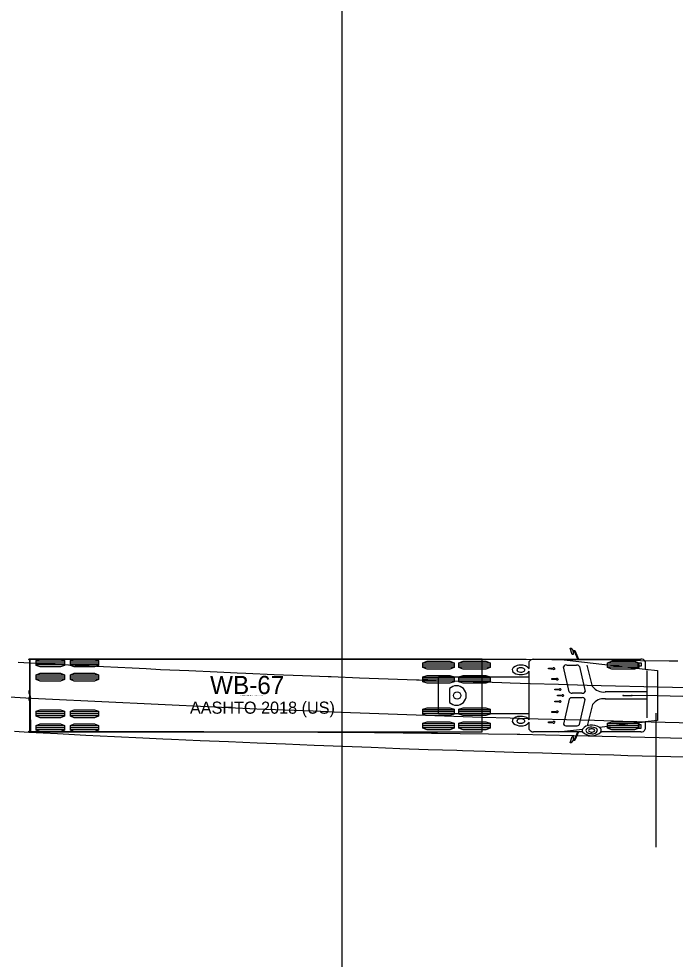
# Model space of a CAD drawing. Extents: x 973688 to 979179, y 703586 to 707602.
# Drawn here: x 977480.7 to 977557.4, y 704315.4 to 704425.4 of the extents above; entities that cross this region are included whole.
import ezdxf

# ---------------------------------------------------------------- set-up
doc = ezdxf.new("R2010")
doc.units = 0
for name, color, linetype in [('0-NPLT', 7, 'Continuous'), ('NO PLOT', 7, 'Continuous'), ('SB Left', 7, 'Continuous')]:
    doc.layers.add(name, color=color, linetype=linetype)

msp = doc.modelspace()

# ---------------------------------------------------------------- linework, layer by layer
at = {"layer": '0-NPLT'}
for points in [[(977480.64, 704350.16), (977483.97, 704349.98), (977484.96, 704349.93), (977487.29, 704349.81), (977490.62, 704349.65), (977493.94, 704349.49), (977495.6, 704349.41), (977497.26, 704349.33), (977500.59, 704349.18), (977503.91, 704349.03), (977506.24, 704348.93), (977507.24, 704348.88), (977510.56, 704348.74), (977513.89, 704348.61), (977516.88, 704348.49), (977517.21, 704348.48), (977520.54, 704348.35), (977523.87, 704348.23), (977527.19, 704348.11), (977527.52, 704348.1), (977530.52, 704348), (977533.84, 704347.89), (977537.17, 704347.78), (977538.16, 704347.75), (977540.49, 704347.68), (977543.82, 704347.58), (977547.14, 704347.49), (977548.8, 704347.45), (977550.47, 704347.4), (977553.79, 704347.32), (977557.12, 704347.24), (977559.78, 704347.18)], [(977558.6, 704339.07), (977555.26, 704339.15), (977551.92, 704339.23), (977550.26, 704339.28), (977548.59, 704339.32), (977545.25, 704339.41), (977541.92, 704339.51), (977538.58, 704339.61), (977535.25, 704339.71), (977532.58, 704339.8), (977531.91, 704339.82), (977528.58, 704339.93), (977525.24, 704340.05), (977521.9, 704340.17), (977518.57, 704340.29), (977515.23, 704340.42), (977511.9, 704340.56), (977508.56, 704340.69), (977505.22, 704340.84), (977501.89, 704340.98), (977498.55, 704341.13), (977497.55, 704341.18), (977495.22, 704341.29), (977491.88, 704341.45), (977488.55, 704341.61), (977485.21, 704341.78), (977481.88, 704341.95), (977480.21, 704342.04)]]:
    msp.add_lwpolyline(points, dxfattribs=at)
msp.add_arc((977617.27, 706926.99), 2584.55, 266.85786, 271.5329, dxfattribs=at)
at = {"layer": 'NO PLOT'}
msp.add_lwpolyline([(977518.51, 704645.43), (978198.51, 704645.43), (978198.51, 704205.43), (977518.51, 704205.43)], close=True, dxfattribs=at)
at = {"layer": 'SB Left'}
for p, q in [((977545.42, 704351.08), (977545.16, 704351.8)), ((977545.16, 704351.8), (977545.17, 704351.8)), ((977545.17, 704351.8), (977545.28, 704351.8)), ((977545.28, 704351.8), (977545.29, 704351.8)), ((977545.29, 704351.8), (977545.52, 704351.48)), ((977545.52, 704351.08), (977545.42, 704351.08)), ((977545.52, 704351.48), (977545.53, 704351.48)), ((977545.54, 704351.43), (977545.52, 704351.08)), ((977545.54, 704351.46), (977545.53, 704351.48)), ((977545.53, 704351.48), (977545.61, 704351.48)), ((977545.54, 704351.43), (977545.54, 704351.46)), ((977545.62, 704351.43), (977545.54, 704351.43)), ((977545.54, 704351.43), (977545.54, 704351.43)), ((977545.66, 704351.42), (977545.62, 704351.43)), ((977545.62, 704351.43), (977545.62, 704351.43)), ((977545.62, 704351.43), (977545.62, 704351.43)), ((977546.06, 704350.52), (977545.66, 704351.42)), ((977545.66, 704351.42), (977545.66, 704351.42)), ((977545.75, 704351.44), (977546.16, 704350.53)), ((977482.02, 704350.52), (977481.95, 704350.52)), ((977481.95, 704350.52), (977481.95, 704350.5)), ((977481.95, 704350.48), (977481.95, 704350.48)), ((977481.95, 704350.48), (977481.95, 704346.84)), ((977482.02, 704342.02), (977482.02, 704350.52)), ((977487.68, 704350.52), (977482.02, 704350.52)), ((977486.03, 704350.29), (977482.73, 704350.29)), ((977486.03, 704350.07), (977482.73, 704350.07)), ((977486.03, 704349.84), (977482.73, 704349.84)), ((977490.03, 704350.29), (977486.73, 704350.29)), ((977490.03, 704350.07), (977486.73, 704350.07)), ((977490.03, 704349.84), (977486.73, 704349.84)), ((977534.88, 704350.52), (977487.68, 704350.52)), ((977531.61, 704350.04), (977527.94, 704350.04)), ((977531.61, 704349.82), (977527.94, 704349.82)), ((977535.81, 704350.04), (977532.14, 704350.04)), ((977535.81, 704349.82), (977532.14, 704349.82)), ((977534.88, 704346.27), (977534.88, 704350.52)), ((977540.38, 704349.41), (977540.38, 704350.25)), ((977540.89, 704350.52), (977546.06, 704350.52)), ((977543.82, 704350.52), (977553.95, 704349.36)), ((977544.77, 704349.83), (977545.9, 704349.83)), ((977546.06, 704350.52), (977546.17, 704350.52)), ((977546.16, 704350.53), (977546.17, 704350.52)), ((977546.17, 704350.52), (977553.43, 704350.52)), ((977547.8, 704347.34), (977547.17, 704349.81)), ((977553.21, 704350.04), (977549.54, 704350.04)), ((977553.21, 704349.82), (977549.54, 704349.82)), ((977553.11, 704350.11), (977553.47, 704350.11)), ((977553.11, 704349.7), (977553.11, 704350.11)), ((977553.47, 704350.11), (977553.47, 704349.7)), ((977553.95, 704350.23), (977553.95, 704349.37)), ((977531.61, 704349.59), (977527.94, 704349.59)), ((977535.81, 704349.59), (977532.14, 704349.59)), ((977540.38, 704348.44), (977540.38, 704349.13)), ((977542.65, 704349.46), (977543.2, 704349.5)), ((977542.65, 704349.37), (977542.65, 704349.46)), ((977543.2, 704349.33), (977542.65, 704349.37)), ((977545.04, 704346.7), (977544.4, 704349.63)), ((977546.27, 704349.67), (977546.91, 704346.73)), ((977553.21, 704349.59), (977549.54, 704349.59)), ((977553.47, 704349.7), (977553.11, 704349.7)), ((977553.95, 704349.37), (977553.95, 704349.36)), ((977553.95, 704349.36), (977555.38, 704349.2)), ((977554.17, 704343.64), (977554.17, 704349.2)), ((977555.38, 704349.2), (977555.38, 704349.14)), ((977555.38, 704349.14), (977555.38, 704346.27)), ((977486.03, 704348.64), (977482.73, 704348.64)), ((977486.03, 704348.42), (977482.73, 704348.42)), ((977486.03, 704348.19), (977482.73, 704348.19)), ((977490.03, 704348.64), (977486.73, 704348.64)), ((977490.03, 704348.42), (977486.73, 704348.42)), ((977490.03, 704348.19), (977486.73, 704348.19)), ((977531.61, 704348.39), (977527.94, 704348.39)), ((977531.61, 704348.17), (977527.94, 704348.17)), ((977531.61, 704347.94), (977527.94, 704347.94)), ((977529.78, 704346.27), (977529.78, 704348.44)), ((977529.78, 704348.44), (977540.14, 704348.44)), ((977535.81, 704348.39), (977532.14, 704348.39)), ((977535.81, 704348.17), (977532.14, 704348.17)), ((977535.81, 704347.94), (977532.14, 704347.94)), ((977540.14, 704348.44), (977540.38, 704348.44)), ((977540.38, 704344.11), (977540.38, 704348.44)), ((977543.04, 704348.24), (977543.61, 704348.28)), ((977543.04, 704348.15), (977543.04, 704348.24)), ((977543.61, 704348.11), (977543.04, 704348.15)), ((977481.95, 704346.8), (977481.88, 704346.8)), ((977481.88, 704346.8), (977481.88, 704346.8)), ((977481.88, 704346.8), (977481.88, 704346.54)), ((977481.95, 704346.84), (977481.95, 704346.8)), ((977481.95, 704346.54), (977481.95, 704346.8)), ((977481.95, 704346.53), (977481.95, 704346.01)), ((977531.07, 704347.08), (977531.07, 704345.46)), ((977543.37, 704347.02), (977543.92, 704347.06)), ((977543.37, 704346.94), (977543.37, 704347.02)), ((977543.92, 704346.9), (977543.37, 704346.94)), ((977546.54, 704346.53), (977545.41, 704346.53)), ((977554.17, 704346.69), (977549.28, 704346.69)), ((977481.88, 704346.01), (977481.88, 704345.74)), ((977481.88, 704345.74), (977481.88, 704345.74)), ((977481.88, 704345.74), (977481.95, 704345.74)), ((977481.95, 704346.27), (977482.02, 704346.27)), ((977481.95, 704345.74), (977481.95, 704346.01)), ((977481.95, 704345.74), (977481.95, 704345.71)), ((977481.95, 704345.71), (977481.95, 704342.07)), ((977529.78, 704344.11), (977529.78, 704346.27)), ((977534.88, 704342.02), (977534.88, 704346.27)), ((977543.37, 704345.61), (977543.92, 704345.65)), ((977543.37, 704345.52), (977543.37, 704345.61)), ((977543.92, 704345.48), (977543.37, 704345.52)), ((977543.68, 704346.32), (977544.23, 704346.36)), ((977543.68, 704346.23), (977543.68, 704346.32)), ((977544.23, 704346.19), (977543.68, 704346.23)), ((977545.04, 704345.85), (977544.4, 704342.91)), ((977546.54, 704346.01), (977545.41, 704346.01)), ((977546.27, 704342.88), (977546.91, 704345.82)), ((977554.17, 704345.86), (977549.28, 704345.86)), ((977555.38, 704346.27), (977555.38, 704343.41)), ((977486.03, 704344.36), (977482.73, 704344.36)), ((977490.03, 704344.36), (977486.73, 704344.36)), ((977531.61, 704344.61), (977527.94, 704344.61)), ((977531.61, 704344.38), (977527.94, 704344.38)), ((977535.81, 704344.61), (977532.14, 704344.61)), ((977535.81, 704344.38), (977532.14, 704344.38)), ((977543.04, 704344.39), (977543.58, 704344.43)), ((977543.04, 704344.3), (977543.04, 704344.39)), ((977543.58, 704344.27), (977543.04, 704344.3)), ((977547.8, 704345.2), (977547.17, 704342.72)), ((977486.03, 704344.13), (977482.73, 704344.13)), ((977486.03, 704343.9), (977482.73, 704343.9)), ((977490.03, 704344.13), (977486.73, 704344.13)), ((977490.03, 704343.9), (977486.73, 704343.9)), ((977531.61, 704344.15), (977527.94, 704344.15)), ((977540.14, 704344.11), (977529.78, 704344.11)), ((977535.81, 704344.15), (977532.14, 704344.15)), ((977540.38, 704344.11), (977540.14, 704344.11)), ((977540.38, 704343.42), (977540.38, 704344.11)), ((977542.65, 704343.18), (977543.2, 704343.22)), ((977555.38, 704343.35), (977553.95, 704343.18)), ((977555.19, 704344.19), (977555.19, 704328.54)), ((977555.38, 704343.41), (977555.38, 704343.35)), ((977486.03, 704342.71), (977482.73, 704342.71)), ((977486.03, 704342.48), (977482.73, 704342.48)), ((977486.03, 704342.25), (977482.73, 704342.25)), ((977490.03, 704342.71), (977486.73, 704342.71)), ((977490.03, 704342.48), (977486.73, 704342.48)), ((977490.03, 704342.25), (977486.73, 704342.25)), ((977531.61, 704342.96), (977527.94, 704342.96)), ((977531.61, 704342.73), (977527.94, 704342.73)), ((977531.61, 704342.5), (977527.94, 704342.5)), ((977535.81, 704342.96), (977532.14, 704342.96)), ((977535.81, 704342.73), (977532.14, 704342.73)), ((977535.81, 704342.5), (977532.14, 704342.5)), ((977540.38, 704342.29), (977540.38, 704343.14)), ((977542.65, 704343.09), (977542.65, 704343.18)), ((977543.2, 704343.05), (977542.65, 704343.09)), ((977543.82, 704342.02), (977546.6, 704342.34)), ((977544.77, 704342.72), (977545.9, 704342.72)), ((977548.56, 704342.57), (977553.95, 704343.18)), ((977553.21, 704342.96), (977549.54, 704342.96)), ((977553.21, 704342.73), (977549.54, 704342.73)), ((977553.21, 704342.5), (977549.54, 704342.5)), ((977553.47, 704342.85), (977553.11, 704342.85)), ((977553.11, 704342.85), (977553.11, 704342.43)), ((977553.11, 704342.43), (977553.47, 704342.43)), ((977553.47, 704342.43), (977553.47, 704342.85)), ((977553.95, 704343.18), (977553.95, 704343.18)), ((977553.95, 704343.18), (977553.95, 704342.32)), ((977481.95, 704342.07), (977481.95, 704342.07)), ((977481.95, 704342.05), (977481.95, 704342.02)), ((977481.95, 704342.02), (977482.02, 704342.02)), ((977482.02, 704342.02), (977487.68, 704342.02)), ((977487.68, 704342.02), (977534.88, 704342.02)), ((977546.06, 704342.02), (977540.89, 704342.02)), ((977545.16, 704340.74), (977545.42, 704341.46)), ((977545.52, 704341.06), (977545.29, 704340.74)), ((977545.42, 704341.46), (977545.52, 704341.46)), ((977545.52, 704341.46), (977545.54, 704341.12)), ((977545.53, 704341.06), (977545.52, 704341.06)), ((977545.54, 704341.09), (977545.53, 704341.06)), ((977545.61, 704341.06), (977545.53, 704341.06)), ((977545.54, 704341.12), (977545.54, 704341.11)), ((977545.54, 704341.11), (977545.62, 704341.12)), ((977545.54, 704341.11), (977545.54, 704341.09)), ((977545.62, 704341.12), (977545.66, 704341.13)), ((977545.62, 704341.12), (977545.62, 704341.12)), ((977545.62, 704341.12), (977545.62, 704341.12)), ((977545.66, 704341.13), (977546.06, 704342.02)), ((977545.66, 704341.13), (977545.66, 704341.13)), ((977546.16, 704342.01), (977545.75, 704341.11)), ((977546.06, 704342.02), (977546.17, 704342.02)), ((977546.17, 704342.02), (977546.16, 704342.01)), ((977546.6, 704342.02), (977546.17, 704342.02)), ((977553.43, 704342.02), (977548.78, 704342.02)), ((977545.17, 704340.74), (977545.16, 704340.74)), ((977545.28, 704340.74), (977545.17, 704340.74)), ((977545.29, 704340.74), (977545.28, 704340.74))]:
    msp.add_line(p, q, dxfattribs=at)
for points in [[(977481.99, 704350.52), (977482.88, 704350.52), (977483.99, 704350.52), (977485.1, 704350.52), (977486.21, 704350.52), (977487.32, 704350.52), (977489.99, 704350.52), (977493.32, 704350.52), (977496.65, 704350.52), (977499.99, 704350.52), (977503.32, 704350.52), (977506.65, 704350.52), (977509.99, 704350.52), (977513.32, 704350.52), (977516.66, 704350.52), (977519.99, 704350.52), (977523.33, 704350.52), (977526.66, 704350.52), (977530, 704350.52), (977533.34, 704350.52), (977535.68, 704350.52), (977536.68, 704350.52), (977540.02, 704350.51), (977543.02, 704350.5), (977543.36, 704350.5), (977546.7, 704350.47), (977550.05, 704350.43), (977550.38, 704350.43), (977553.4, 704350.38), (977556.74, 704350.32), (977557.75, 704350.31)], [(977558.21, 704341.25), (977555.56, 704341.32), (977552.24, 704341.41), (977548.92, 704341.49), (977545.6, 704341.56), (977542.28, 704341.63), (977539.29, 704341.69), (977538.96, 704341.69), (977535.63, 704341.75), (977532.3, 704341.8), (977529.64, 704341.83), (977528.97, 704341.84), (977525.64, 704341.88), (977522.31, 704341.91), (977519.98, 704341.93), (977518.98, 704341.94), (977515.65, 704341.96), (977512.32, 704341.98), (977509.65, 704341.99), (977508.99, 704341.99), (977505.65, 704342), (977502.32, 704342.01), (977498.99, 704342.02), (977495.65, 704342.02), (977492.32, 704342.02), (977488.99, 704342.02), (977486.99, 704342.02), (977485.88, 704342.02), (977484.76, 704342.02), (977483.65, 704342.02), (977482.54, 704342.02), (977482.1, 704342.02), (977481.99, 704350.52)], [(977551.38, 704346.27), (977551.71, 704346.27), (977552.04, 704346.27), (977552.38, 704346.27)]]:
    msp.add_lwpolyline(points, dxfattribs=at)
for points in [[(977486.03, 704350.35), (977486.03, 704349.78), (977485.56, 704349.61), (977483.19, 704349.61), (977482.73, 704349.78), (977482.73, 704350.35), (977483.19, 704350.52), (977485.56, 704350.52)], [(977490.03, 704350.35), (977490.03, 704349.78), (977489.56, 704349.61), (977487.19, 704349.61), (977486.73, 704349.78), (977486.73, 704350.35), (977487.19, 704350.52), (977489.56, 704350.52)], [(977531.61, 704350.1), (977531.61, 704349.53), (977531.1, 704349.36), (977528.46, 704349.36), (977527.94, 704349.53), (977527.94, 704350.1), (977528.46, 704350.27), (977531.1, 704350.27)], [(977535.81, 704350.1), (977535.81, 704349.53), (977535.3, 704349.36), (977532.66, 704349.36), (977532.14, 704349.53), (977532.14, 704350.1), (977532.66, 704350.27), (977535.3, 704350.27)], [(977553.21, 704350.1), (977553.21, 704349.53), (977552.7, 704349.36), (977550.06, 704349.36), (977549.54, 704349.53), (977549.54, 704350.1), (977550.06, 704350.27), (977552.7, 704350.27)], [(977486.03, 704348.7), (977486.03, 704348.13), (977485.56, 704347.96), (977483.19, 704347.96), (977482.73, 704348.13), (977482.73, 704348.7), (977483.19, 704348.87), (977485.56, 704348.87)], [(977490.03, 704348.7), (977490.03, 704348.13), (977489.56, 704347.96), (977487.19, 704347.96), (977486.73, 704348.13), (977486.73, 704348.7), (977487.19, 704348.87), (977489.56, 704348.87)], [(977531.61, 704348.45), (977531.61, 704347.88), (977531.1, 704347.71), (977528.46, 704347.71), (977527.94, 704347.88), (977527.94, 704348.45), (977528.46, 704348.62), (977531.1, 704348.62)], [(977535.81, 704348.45), (977535.81, 704347.88), (977535.3, 704347.71), (977532.66, 704347.71), (977532.14, 704347.88), (977532.14, 704348.45), (977532.66, 704348.62), (977535.3, 704348.62)], [(977486.03, 704344.42), (977486.03, 704343.85), (977485.56, 704343.67), (977483.19, 704343.67), (977482.73, 704343.85), (977482.73, 704344.42), (977483.19, 704344.59), (977485.56, 704344.59)], [(977490.03, 704344.42), (977490.03, 704343.85), (977489.56, 704343.67), (977487.19, 704343.67), (977486.73, 704343.85), (977486.73, 704344.42), (977487.19, 704344.59), (977489.56, 704344.59)], [(977531.61, 704344.67), (977531.61, 704344.1), (977531.1, 704343.92), (977528.46, 704343.92), (977527.94, 704344.1), (977527.94, 704344.67), (977528.46, 704344.84), (977531.1, 704344.84)], [(977535.81, 704344.67), (977535.81, 704344.1), (977535.3, 704343.92), (977532.66, 704343.92), (977532.14, 704344.1), (977532.14, 704344.67), (977532.66, 704344.84), (977535.3, 704344.84)], [(977486.03, 704342.77), (977486.03, 704342.2), (977485.56, 704342.02), (977483.19, 704342.02), (977482.73, 704342.2), (977482.73, 704342.77), (977483.19, 704342.94), (977485.56, 704342.94)], [(977490.03, 704342.77), (977490.03, 704342.2), (977489.56, 704342.02), (977487.19, 704342.02), (977486.73, 704342.2), (977486.73, 704342.77), (977487.19, 704342.94), (977489.56, 704342.94)], [(977531.61, 704343.02), (977531.61, 704342.45), (977531.1, 704342.27), (977528.46, 704342.27), (977527.94, 704342.45), (977527.94, 704343.02), (977528.46, 704343.19), (977531.1, 704343.19)], [(977535.81, 704343.02), (977535.81, 704342.45), (977535.3, 704342.27), (977532.66, 704342.27), (977532.14, 704342.45), (977532.14, 704343.02), (977532.66, 704343.19), (977535.3, 704343.19)], [(977553.21, 704343.02), (977553.21, 704342.45), (977552.7, 704342.27), (977550.06, 704342.27), (977549.54, 704342.45), (977549.54, 704343.02), (977550.06, 704343.19), (977552.7, 704343.19)]]:
    msp.add_lwpolyline(points, close=True, dxfattribs=at)
for centre, radius in [((977481.91, 704350.49), 0.0266), ((977531.95, 704346.27), 0.424), ((977551.38, 704346.27), 0.0417), ((977552.38, 704346.27), 0.0417), ((977552.38, 704346.27), 0.0417), ((977481.91, 704342.06), 0.0266)]:
    msp.add_circle(centre, radius, dxfattribs=at)
for centre, radius, start, end in [((977545.68, 704351.4), 0.108, 80.8412, 127.0237), ((977545.7, 704351.45), 0.0522, 346.2628, 91.1174), ((977481.91, 704350.49), 0.0363, 19.0774, 340.2388), ((977539.36, 704348.4), 1.42, 87.9282, 124.996), ((977539.5, 704348.68), 1.14, 39.6299, 94.4212), ((977540.89, 704349.9), 0.619, 89.998, 145.8397), ((977544.7, 704349.51), 0.332, 78.9214, 157.3434), ((977545.95, 704349.45), 0.387, 34.3328, 97.5648), ((977553.5, 704350.04), 0.486, 22.463, 98.4141), ((977538.74, 704349.27), 0.346, 123.3927, 220.4058), ((977539.27, 704349.86), 1.14, 225.764, 267.2847), ((977539.11, 704349.27), 0.172, 120.3016, 207.4522), ((977539.25, 704349.39), 0.362, 214.2966, 263.3375), ((977539.38, 704348.86), 0.664, 84.9038, 123.1255), ((977539.4, 704349.74), 0.732, 255.1738, 301.4083), ((977539.4, 704350.45), 1.73, 263.8266, 288.6251), ((977539.46, 704349), 0.522, 45.0054, 92.1695), ((977539.7, 704349.26), 0.169, 298.4343, 38.553), ((977539.76, 704349.51), 0.729, 285.8085, 328.3225), ((977543.25, 704349.35), 0.157, 23.546, 110.6556), ((977543.24, 704349.51), 0.184, 256.9532, 328.8452), ((977543.64, 704348.13), 0.157, 23.546, 110.6556), ((977543.63, 704348.29), 0.184, 256.9532, 328.8452), ((977481.91, 704346.54), 0.0353, 3.3362, 181.6858), ((977481.91, 704346.54), 0.0352, 180.0253, 359.0257), ((977531.88, 704346.27), 1.14, 225, 135), ((977543.97, 704346.92), 0.157, 23.546, 110.6556), ((977543.96, 704347.08), 0.184, 256.9532, 328.8452), ((977545.36, 704346.92), 0.387, 214.3353, 277.5624), ((977546.63, 704346.82), 0.296, 252.9836, 343.2812), ((977549.06, 704348.19), 1.52, 213.9925, 278.42), ((977481.91, 704346.01), 0.0352, 0.9743, 179.9747), ((977481.91, 704346.01), 0.0354, 184.2915, 356.477), ((977543.96, 704345.47), 0.184, 31.1548, 103.0468), ((977543.97, 704345.63), 0.157, 249.3444, 336.454), ((977544.28, 704346.21), 0.157, 23.546, 110.6556), ((977544.28, 704346.34), 0.157, 249.3444, 336.454), ((977545.36, 704345.63), 0.387, 82.4376, 145.6647), ((977546.63, 704345.73), 0.296, 16.7188, 107.0164), ((977549.06, 704344.36), 1.52, 81.58, 146.0075), ((977532.49, 703135.05), 1211.38, 84.53681, 89.05926), ((977543.63, 704344.25), 0.184, 31.1548, 103.0468), ((977543.64, 704344.41), 0.157, 249.3444, 336.454), ((977538.74, 704343.28), 0.346, 139.5942, 236.6073), ((977539.27, 704342.69), 1.14, 92.7153, 134.236), ((977539.11, 704343.28), 0.172, 152.5478, 239.6984), ((977539.25, 704343.16), 0.362, 96.6625, 145.7034), ((977539.4, 704342.81), 0.732, 58.5917, 104.8262), ((977539.4, 704342.1), 1.73, 71.3749, 96.1734), ((977539.7, 704343.28), 0.169, 321.447, 61.5657), ((977539.76, 704343.04), 0.729, 31.6775, 74.1915), ((977543.24, 704343.04), 0.184, 31.1548, 103.0468), ((977539.36, 704344.15), 1.42, 235.004, 272.0718), ((977539.38, 704343.69), 0.664, 236.8745, 275.0962), ((977539.5, 704343.86), 1.14, 265.5788, 320.3701), ((977539.46, 704343.55), 0.522, 267.8305, 314.9946), ((977540.89, 704342.64), 0.619, 214.1603, 270.002), ((977543.25, 704343.19), 0.157, 249.3444, 336.454), ((977544.7, 704343.04), 0.332, 202.6566, 281.0786), ((977545.95, 704343.1), 0.387, 262.4352, 325.6672), ((977546.91, 704342.18), 0.347, 152.3272, 207.1378), ((977547.51, 704341.65), 1.14, 88.7045, 142.5071), ((977547.43, 704342.07), 0.44, 101.7942, 165.6071), ((977547.32, 704342.21), 0.317, 185.8502, 247.4426), ((977547.58, 704342.1), 0.263, 88.9349, 162.8368), ((977547.5, 704342.2), 0.17, 187.6691, 241.7334), ((977547.68, 704341.37), 1.19, 71.1312, 107.0205), ((977547.7, 704341.09), 1.7, 59.9207, 95.8288), ((977547.68, 704341.8), 0.575, 63.0751, 99.6454), ((977547.79, 704342.43), 0.634, 260.5839, 336.5856), ((977547.82, 704342.23), 0.223, 277.2349, 346.8374), ((977547.88, 704342.17), 0.158, 4.9712, 66.484), ((977548.01, 704342.13), 0.366, 8.0523, 80.5333), ((977548.38, 704342.18), 0.425, 338.0629, 64.5993), ((977553.5, 704342.5), 0.486, 261.5859, 337.537), ((977479.92, 704342.05), 2.02, 0, 0.6838), ((977545.68, 704341.15), 0.108, 232.9763, 279.1588), ((977545.7, 704341.1), 0.0522, 268.8826, 13.7372), ((977547.69, 704343.1), 1.53, 224.4927, 315.5018), ((977547.66, 704342.84), 1.03, 242.8237, 271.2102), ((977547.69, 704342.58), 0.589, 242.7555, 285.7382)]:
    msp.add_arc(centre, radius, start, end, dxfattribs=at)
for centre, major_axis, start_param, end_param in [((977545.68, 704351.46), (0.0782, 0), 2.615166, 3.884468), ((977545.68, 704351.46), (-0.0782, 0), 1.301202, 2.571945), ((977545.68, 704341.09), (0.0782, 0), 2.398717, 3.668019), ((977545.68, 704341.09), (0.0782, 0), 0.569648, 1.840391)]:
    msp.add_ellipse(centre, major_axis=major_axis, ratio=0.544872, start_param=start_param, end_param=end_param, dxfattribs=at)

# ---------------------------------------------------------------- texts
for s, height, p in [('WB-67', 2.125, (977503.06, 704346.44)), ('AASHTO 2018 (US)', 1.4167, (977500.71, 704344.14)), ('(c) 2022 Transoft Solutions, Inc. All rights reserved.', 0.085, (977506.64, 704346.23))]:
    msp.add_text(s, height=height, dxfattribs=at).set_placement(p)

doc.saveas('drawing.dxf')
